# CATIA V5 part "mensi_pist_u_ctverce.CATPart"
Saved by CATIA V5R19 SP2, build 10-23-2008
Part number: mensi_pist_u_ctverce
Bounding box of the stored display mesh (mm): x -79.981 to 79.981, y -73.977 to 75.073, z -79.914 to 79.914
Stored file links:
  C:\Users\Martin\Desktop\9.semestr\Projekt-diplomka\3D model\mensi_pist_u_ctverce.CATPart
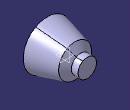
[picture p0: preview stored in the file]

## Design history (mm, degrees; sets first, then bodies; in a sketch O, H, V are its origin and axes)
Body1 (main body)
  Sketch1 on yz-plane, origin (0, 0, 0), H (0, 1, 0), V (0, 0, 1)
    axis line L1 (-86.168, 0) -> (108.7632, 0)
    point P1 (-86.168, 0)
    line L2 (-73.9772, 0) -> (-73.9772, 40)
    point P3 (-73.9772, 0)
    line L3 (-73.9772, 40) -> (-58.9772, 40)
    line L4 (-58.9772, 40) -> (-58.9772, 80)
    point P6 (-58.9772, 80)
    line L5 (-58.9772, 80) -> (34.0842, 55)
    point P7 (34.0842, 55)
    line L6 (34.0842, 55) -> (52.5309, 30.9606)
    line L7 (52.5309, 30.9606) -> (75.0734, 30.9606)
    line L8 (75.0734, 30.9606) -> (75.0734, 0)
    point P10 (75.0734, 0)
    distance L3 L1 = 40
    distance P6 L1 = 80
    distance P7 L1 = 55
    distance L4 L2 = 15
    coincidence: P1 H, P3 L1, P10 L1
    horizontal: L1 H, L3 H, L7 H
    vertical: L2 V, L4 V, L8 V
  Shaft1: profile Sketch1, axis Sketch1.L1, angle 360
